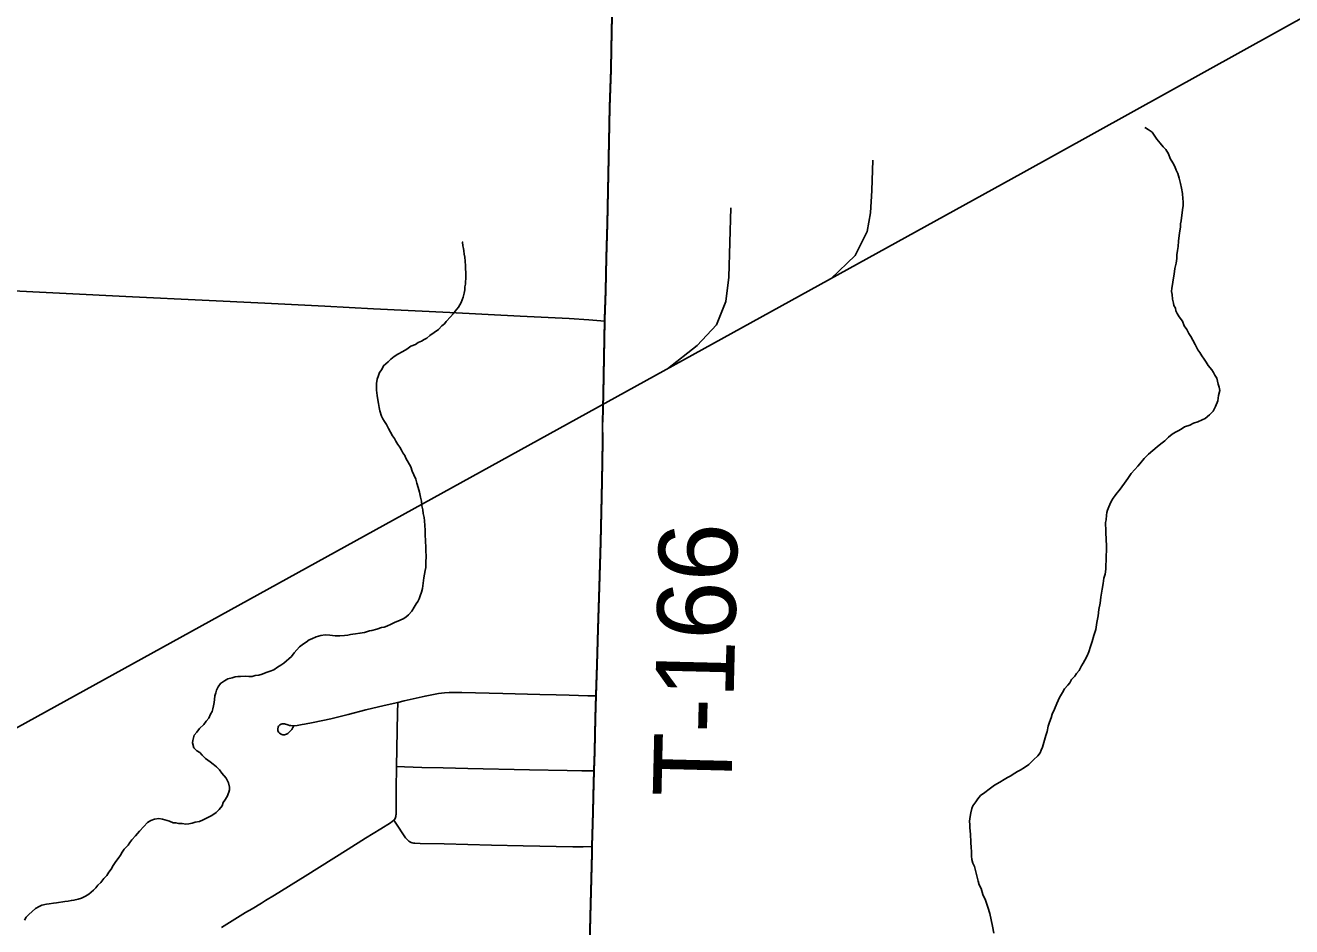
# Model space of a CAD drawing. Extents: x 0 to 34, y 0 to 22.
# Drawn here: x 28.463 to 29.379, y 19.256 to 19.908 of the extents above; entities that cross this region are included whole.
import ezdxf

# ---------------------------------------------------------------- set-up
doc = ezdxf.new("R2010")
doc.units = 0
for name, color, linetype in [('GM_X_City_Street', 7, 'Continuous'), ('GM_X_Minor_River', 7, 'Continuous'), ('GM_X_Rail_Line', 7, 'Continuous'), ('GM_X_Township_Road', 7, 'Continuous'), ('GM_X_Township_Road_Text', 7, 'Continuous')]:
    doc.layers.add(name, color=color, linetype=linetype)

msp = doc.modelspace()

# ---------------------------------------------------------------- linework, layer by layer
at = {"layer": 'GM_X_City_Street'}
for points in [[(28.13583, 19.73373), (28.14997, 19.7328), (28.17291, 19.73119), (28.20572, 19.72916), (28.23749, 19.72711), (28.27908, 19.72477), (28.3505, 19.72142), (28.43928, 19.71681), (28.54048, 19.71173), (28.59077, 19.70916), (28.63611, 19.70705), (28.67955, 19.70489), (28.71495, 19.70305), (28.77021, 19.7003), (28.82111, 19.69765), (28.85651, 19.69601), (28.87072, 19.69497), (28.88228, 19.69412)], [(28.65709, 19.40097), (28.65649, 19.39973), (28.65572, 19.39849), (28.65518, 19.39791), (28.65444, 19.39708), (28.65362, 19.39631), (28.65276, 19.39556), (28.65185, 19.39503), (28.65108, 19.39474), (28.65037, 19.39462), (28.64922, 19.39462), (28.64857, 19.39473), (28.64795, 19.39494), (28.64688, 19.39564), (28.6461, 19.39658), (28.64568, 19.39765), (28.6456, 19.39827), (28.64564, 19.39897), (28.64589, 19.40008), (28.64617, 19.4007), (28.64655, 19.40123), (28.647, 19.40169), (28.64798, 19.4023), (28.64862, 19.40249), (28.64926, 19.40259), (28.65049, 19.40255), (28.65288, 19.40173), (28.65403, 19.4014), (28.65502, 19.4012), (28.65646, 19.40108), (28.65953, 19.4013), (28.66319, 19.4019), (28.66499, 19.40229), (28.6711, 19.40344), (28.6839, 19.4062), (28.6966, 19.40927), (28.70924, 19.41259), (28.72256, 19.41568), (28.73245, 19.41802), (28.73709, 19.41911), (28.75224, 19.42262), (28.76199, 19.42452), (28.76612, 19.42501), (28.76961, 19.42521), (28.77871, 19.42523), (28.80856, 19.42455), (28.83528, 19.4238), (28.84709, 19.42342), (28.85641, 19.42315), (28.87008, 19.42289), (28.87602, 19.42278)], [(28.60482, 19.25512), (28.62218, 19.26582), (28.62691, 19.26866), (28.63367, 19.27272), (28.63677, 19.27458), (28.64313, 19.27844), (28.66531, 19.29223), (28.69643, 19.31166), (28.70902, 19.31967), (28.72014, 19.32648), (28.72714, 19.33089), (28.72965, 19.33282), (28.7301, 19.33332), (28.73047, 19.33393), (28.73071, 19.33459), (28.73096, 19.3355), (28.73112, 19.33627), (28.73121, 19.3369), (28.73125, 19.33764), (28.7312, 19.34268), (28.73114, 19.3551), (28.73154, 19.37149), (28.7323, 19.41042), (28.73245, 19.41802)], [(28.73154, 19.37149), (28.73735, 19.37133), (28.74975, 19.371), (28.76525, 19.37067), (28.78323, 19.37022), (28.82786, 19.36919), (28.85514, 19.36882), (28.86568, 19.36857), (28.87464, 19.36835)], [(28.72965, 19.33282), (28.73292, 19.32779), (28.73563, 19.32361), (28.73808, 19.32), (28.73889, 19.319), (28.73975, 19.31816), (28.74037, 19.3176), (28.74112, 19.31707), (28.74202, 19.31661), (28.74295, 19.31633), (28.74371, 19.31612), (28.74477, 19.31599), (28.74851, 19.31597), (28.76592, 19.31562), (28.80014, 19.31469), (28.82316, 19.31427), (28.85924, 19.31355), (28.86671, 19.31356), (28.87322, 19.31358)]]:
    msp.add_lwpolyline(points, dxfattribs=at)
at = {"layer": 'GM_X_Minor_River'}
for points in [[(29.25024, 19.56591), (29.25181, 19.56777), (29.253, 19.56963), (29.25458, 19.57149), (29.25655, 19.57409), (29.25853, 19.5767), (29.2609, 19.58005), (29.26329, 19.58378), (29.26604, 19.58674), (29.268, 19.58896), (29.26957, 19.59082), (29.27272, 19.59453), (29.27586, 19.59786), (29.27897, 19.60043), (29.28209, 19.603), (29.28481, 19.6052), (29.28753, 19.60741), (29.29027, 19.60999), (29.29299, 19.61219), (29.29531, 19.61364), (29.29724, 19.61473), (29.29955, 19.6158), (29.30189, 19.61763), (29.30571, 19.61866), (29.30842, 19.6201), (29.31149, 19.62116), (29.31457, 19.62259), (29.31687, 19.62366), (29.31999, 19.62623), (29.32272, 19.62881), (29.32434, 19.63219), (29.32598, 19.63632), (29.32647, 19.64011), (29.32734, 19.64388), (29.32703, 19.64617), (29.32634, 19.64847), (29.32532, 19.65268), (29.32387, 19.65501), (29.32278, 19.65694), (29.3217, 19.65887), (29.31913, 19.66198), (29.31768, 19.66431), (29.31623, 19.66663), (29.3144, 19.66896), (29.31295, 19.67129), (29.31148, 19.67323), (29.3097, 19.67708), (29.30789, 19.68017), (29.30645, 19.68288), (29.305, 19.6852), (29.30356, 19.6879), (29.30174, 19.69062), (29.30032, 19.69408), (29.29813, 19.69718), (29.29668, 19.69951), (29.29559, 19.70144), (29.29527, 19.70335), (29.29419, 19.70528), (29.29386, 19.70719), (29.29318, 19.70987), (29.2929, 19.7133), (29.29259, 19.71559), (29.29266, 19.71787), (29.29311, 19.72051), (29.29359, 19.72392), (29.29447, 19.72808), (29.29497, 19.73224), (29.29585, 19.73602), (29.29632, 19.73943), (29.2964, 19.74208), (29.29687, 19.74511), (29.29734, 19.74814), (29.29745, 19.75194), (29.29795, 19.7561), (29.29843, 19.75951), (29.29889, 19.76216), (29.29895, 19.76444), (29.2994, 19.7667), (29.30039, 19.77466), (29.30086, 19.77768), (29.30095, 19.78072), (29.30063, 19.78263), (29.30036, 19.78644), (29.29971, 19.79026), (29.29905, 19.7937), (29.29802, 19.79753), (29.29698, 19.80098), (29.29591, 19.80329), (29.29485, 19.80598), (29.29341, 19.80869), (29.2916, 19.81178), (29.29018, 19.81524), (29.28837, 19.81834), (29.28653, 19.82029), (29.28433, 19.82301), (29.28175, 19.82575), (29.27848, 19.83078), (29.2755, 19.83277), (29.27364, 19.83396), (29.27327, 19.83436)], [(28.75083, 19.50433), (28.75132, 19.50812), (28.75178, 19.51077), (28.75224, 19.51341), (28.75269, 19.51568), (28.75274, 19.51758), (28.75282, 19.52024), (28.75289, 19.5229), (28.75295, 19.5248), (28.75263, 19.52671), (28.75268, 19.52861), (28.75275, 19.53089), (28.75247, 19.53431), (28.75253, 19.53621), (28.7522, 19.53812), (28.75227, 19.5404), (28.75233, 19.54268), (28.75205, 19.54611), (28.75177, 19.54954), (28.75146, 19.55183), (28.75079, 19.55489), (28.75049, 19.55756), (28.74981, 19.56024), (28.74953, 19.56367), (28.74886, 19.56673), (28.7482, 19.57017), (28.74716, 19.57362), (28.74611, 19.57669), (28.74544, 19.57975), (28.74401, 19.58283), (28.74295, 19.58552), (28.7419, 19.5886), (28.73828, 19.59478), (28.73758, 19.5967), (28.73611, 19.59865), (28.73503, 19.60058), (28.73396, 19.60289), (28.7325, 19.60483), (28.73104, 19.60715), (28.72996, 19.60909), (28.7285, 19.61103), (28.72706, 19.61373), (28.72562, 19.61643), (28.72418, 19.61914), (28.72272, 19.62146), (28.72164, 19.62339), (28.72056, 19.62532), (28.71953, 19.62915), (28.71884, 19.63145), (28.71855, 19.6345), (28.71786, 19.63718), (28.71757, 19.64023), (28.71725, 19.64214), (28.71693, 19.64405), (28.71698, 19.64595), (28.71707, 19.64899), (28.71754, 19.65202), (28.71838, 19.65465), (28.7192, 19.65691), (28.72078, 19.65914), (28.722, 19.66177), (28.72551, 19.66471), (28.72746, 19.66655), (28.72979, 19.66839), (28.7325, 19.67021), (28.73597, 19.67201), (28.73907, 19.67382), (28.74179, 19.67602), (28.74524, 19.67706), (28.74718, 19.67853), (28.74949, 19.6796), (28.75142, 19.68069), (28.75335, 19.68177), (28.75569, 19.6836), (28.76189, 19.68798), (28.76425, 19.69058), (28.76619, 19.69204), (28.76738, 19.69391), (28.77052, 19.69724), (28.77248, 19.69946), (28.77406, 19.70132), (28.77642, 19.70429), (28.77842, 19.70765), (28.77967, 19.71142), (28.78052, 19.71443), (28.78096, 19.7167), (28.78103, 19.71898), (28.78146, 19.72087), (28.78152, 19.72277), (28.78157, 19.72466), (28.78163, 19.72656), (28.78171, 19.72922), (28.78141, 19.73189), (28.78147, 19.73417), (28.78119, 19.7376), (28.78089, 19.74027), (28.78058, 19.74256), (28.78027, 19.74485), (28.77994, 19.74676), (28.77962, 19.74867), (28.77932, 19.75134)], [(28.77932, 19.75134), (28.77932, 19.75134), (28.77894, 19.75135)], [(29.16395, 19.251), (29.16295, 19.25598), (29.16195, 19.26057), (29.16094, 19.26516), (29.15956, 19.26976), (29.1578, 19.27475), (29.15602, 19.27898), (29.15463, 19.28321), (29.15319, 19.28591), (29.15251, 19.28859), (29.14978, 19.29931), (29.14871, 19.30162), (29.14803, 19.3043), (29.14771, 19.30659), (29.14781, 19.31001), (29.14752, 19.31306), (29.14724, 19.31649), (29.14731, 19.31877), (29.14698, 19.32068), (29.14704, 19.32258), (29.14673, 19.32487), (29.14642, 19.32754), (29.14648, 19.32944), (29.14618, 19.33211), (29.14666, 19.33552), (29.14711, 19.33816), (29.14796, 19.34118), (29.14878, 19.34306), (29.15076, 19.34604), (29.15235, 19.34827), (29.15431, 19.3505), (29.15741, 19.35269), (29.16053, 19.35526), (29.16441, 19.35819), (29.16827, 19.36036), (29.17136, 19.36217), (29.17368, 19.36362), (29.17561, 19.36471), (29.1791, 19.36689), (29.18103, 19.36797), (29.18296, 19.36906), (29.18605, 19.37087), (29.18915, 19.37306), (29.19267, 19.37638), (29.19579, 19.37933), (29.19738, 19.38156), (29.19819, 19.38344), (29.19902, 19.3857), (29.20154, 19.39399), (29.20239, 19.397), (29.20326, 19.40078), (29.2041, 19.4038), (29.20533, 19.4068), (29.20617, 19.40944), (29.2078, 19.41319), (29.20944, 19.41733), (29.21146, 19.42145), (29.21346, 19.42519), (29.21506, 19.42781), (29.21741, 19.4304), (29.21899, 19.43226), (29.22019, 19.4345), (29.22255, 19.43709), (29.22374, 19.43896), (29.22571, 19.44118), (29.22732, 19.44456), (29.22852, 19.44642), (29.22972, 19.44867), (29.23133, 19.45166), (29.23256, 19.45467), (29.23381, 19.45844), (29.23505, 19.4622), (29.23632, 19.46634), (29.23759, 19.47087), (29.23849, 19.47579), (29.23939, 19.4807), (29.23991, 19.48525), (29.2408, 19.48978), (29.24131, 19.49433), (29.24223, 19.5), (29.24312, 19.50416), (29.24361, 19.50795), (29.24445, 19.51096), (29.24493, 19.51437), (29.24502, 19.51741), (29.24512, 19.52083), (29.24522, 19.52425), (29.24533, 19.52804), (29.24542, 19.53108), (29.24495, 19.54098), (29.24504, 19.54402), (29.24472, 19.54631), (29.24478, 19.54821), (29.24521, 19.55009), (29.24532, 19.55351), (29.24575, 19.5554), (29.24619, 19.55729), (29.24701, 19.55954), (29.24782, 19.56142), (29.24904, 19.56405), (29.25024, 19.56591)], [(28.6009, 19.33836), (28.60324, 19.34058), (28.60521, 19.34318), (28.60604, 19.34544), (28.60723, 19.34731), (28.60883, 19.34992), (28.61006, 19.35293), (28.61049, 19.35481), (28.61055, 19.35671), (28.60988, 19.35977), (28.60808, 19.36325), (28.60514, 19.36675), (28.60331, 19.36909), (28.6011, 19.37143), (28.59888, 19.3734), (28.59664, 19.37498), (28.59329, 19.37736), (28.59071, 19.37971), (28.58924, 19.38166), (28.587, 19.38286), (28.58479, 19.38521), (28.58375, 19.38866), (28.58418, 19.39055), (28.58462, 19.39243), (28.58505, 19.39432), (28.58702, 19.39655), (28.58899, 19.39915), (28.59212, 19.4021), (28.5937, 19.40434), (28.59567, 19.40656), (28.59689, 19.40957), (28.59809, 19.41143), (28.59852, 19.41332), (28.59897, 19.41559), (28.59941, 19.41786), (28.59986, 19.42012), (28.59994, 19.42278), (28.60076, 19.42504), (28.6012, 19.42693), (28.6024, 19.42917), (28.604, 19.43179), (28.60709, 19.4336), (28.60941, 19.43505), (28.61247, 19.43573), (28.61477, 19.43642), (28.61668, 19.43674), (28.61857, 19.43669), (28.622, 19.43697), (28.62466, 19.43689), (28.62694, 19.43683), (28.62923, 19.43752), (28.6319, 19.43782), (28.6342, 19.43852), (28.63727, 19.43957), (28.63996, 19.44063), (28.64265, 19.4417), (28.64536, 19.44352), (28.64768, 19.44497), (28.65001, 19.44643), (28.65546, 19.45121), (28.65744, 19.45381), (28.6594, 19.45604), (28.66137, 19.45826), (28.66409, 19.46046), (28.66602, 19.46155), (28.66835, 19.46338), (28.67027, 19.46409), (28.67335, 19.46552), (28.6768, 19.46656), (28.67985, 19.46685), (28.68327, 19.46675), (28.68705, 19.46626), (28.69047, 19.46616), (28.69389, 19.46644), (28.69618, 19.46676), (28.69809, 19.46708), (28.7, 19.46741), (28.70191, 19.46773), (28.70495, 19.46803), (28.70839, 19.46869), (28.71184, 19.46973), (28.71375, 19.47005), (28.7172, 19.47109), (28.72065, 19.47213), (28.72256, 19.47246), (28.72448, 19.47316), (28.72756, 19.47459), (28.73064, 19.47603), (28.73256, 19.47673), (28.73641, 19.47852), (28.73834, 19.47961), (28.74029, 19.48145), (28.74265, 19.48404), (28.74425, 19.48704), (28.74584, 19.48927), (28.74703, 19.49114), (28.74785, 19.49302), (28.74867, 19.49527), (28.74951, 19.49791), (28.75034, 19.50055), (28.75083, 19.50433)], [(28.46226, 19.26025), (28.46346, 19.2625), (28.46542, 19.26434), (28.46776, 19.26656), (28.4701, 19.26877), (28.4728, 19.27021), (28.47473, 19.2713), (28.47817, 19.27196), (28.48008, 19.27228), (28.48313, 19.27258), (28.48542, 19.27289), (28.49152, 19.27385), (28.49381, 19.27417), (28.4961, 19.27448), (28.49801, 19.27481), (28.50107, 19.27548), (28.50336, 19.27617), (28.50645, 19.27761), (28.50877, 19.27906), (28.51227, 19.282), (28.51384, 19.28385), (28.51542, 19.28571), (28.51737, 19.28755), (28.51974, 19.29053), (28.5217, 19.29275), (28.52328, 19.29499), (28.52487, 19.29722), (28.52646, 19.29984), (28.52845, 19.30282), (28.53003, 19.30506), (28.53162, 19.30729), (28.53282, 19.30954), (28.53441, 19.31177), (28.53715, 19.31473), (28.53835, 19.3166), (28.53992, 19.31846), (28.54267, 19.32142), (28.54542, 19.32476), (28.54856, 19.32809), (28.5513, 19.33105), (28.55362, 19.33251), (28.55631, 19.33357), (28.55936, 19.33386), (28.56201, 19.3334), (28.56729, 19.33211), (28.56991, 19.3309), (28.57181, 19.33084), (28.5737, 19.33041), (28.57635, 19.33033), (28.579, 19.32987), (28.58129, 19.33019), (28.58357, 19.3305), (28.58587, 19.3312), (28.58893, 19.33187), (28.59162, 19.33293), (28.59355, 19.33401), (28.59586, 19.33509), (28.59779, 19.33617), (28.6009, 19.33836)]]:
    msp.add_lwpolyline(points, dxfattribs=at)
at = {"layer": 'GM_X_Rail_Line'}
for points in [[(26.77525, 17.99218), (26.84574, 18.02958), (26.89547, 18.06061), (26.9486, 18.09333), (26.99087, 18.12212), (27.08532, 18.1905), (27.21214, 18.29488), (27.38363, 18.4394), (27.44818, 18.50107), (27.48656, 18.54586), (27.5232, 18.586), (27.56216, 18.66395), (27.58616, 18.71125), (27.67905, 18.89432), (27.70173, 18.94027), (27.72383, 18.97169), (27.75291, 18.99728), (27.81688, 19.03917), (28.26175, 19.29222), (29.18349, 19.80066), (29.90227, 20.19973)], [(29.04581, 19.7247), (29.06345, 19.74153), (29.07216, 19.75892), (29.0746, 19.77244), (29.07555, 19.78876), (29.0763, 19.81063)], [(28.92772, 19.65955), (28.94917, 19.67635), (28.9631, 19.69148), (28.96994, 19.70829), (28.97215, 19.72582), (28.97349, 19.77604)]]:
    msp.add_lwpolyline(points, dxfattribs=at)
at = {"layer": 'GM_X_Township_Road'}
msp.add_line((28.87407, 19.34975), (28.87464, 19.36835), dxfattribs=at)
for points in [[(28.88228, 19.69412), (28.88229, 19.69519), (28.88298, 19.7157), (28.88355, 19.73994), (28.8842, 19.76417), (28.885, 19.80021), (28.88532, 19.82384), (28.88598, 19.84871), (28.88677, 19.87606), (28.88719, 19.89097), (28.88789, 19.927), (28.88866, 19.95622), (28.88971, 19.99363), (28.89045, 20.03607)], [(28.87109, 19.24332), (28.87156, 19.26305), (28.87287, 19.309), (28.87298, 19.31413), (28.87352, 19.33882), (28.87383, 19.3503), (28.8744, 19.3689), (28.87479, 19.38277), (28.87532, 19.40699), (28.87579, 19.42333), (28.8758, 19.42375), (28.87642, 19.44548), (28.8773, 19.47155), (28.87815, 19.50196), (28.87906, 19.53423), (28.88002, 19.5783), (28.88052, 19.60748), (28.88049, 19.62075), (28.88099, 19.64166), (28.88204, 19.69467), (28.88206, 19.69574), (28.88275, 19.71625), (28.88331, 19.74049), (28.88396, 19.76472), (28.88476, 19.80077), (28.88509, 19.82439), (28.88574, 19.84926), (28.88654, 19.87661), (28.88696, 19.89152), (28.88765, 19.92756)], [(28.88765, 19.92756), (28.88696, 19.89152), (28.88654, 19.87661), (28.88574, 19.84926), (28.88509, 19.82439), (28.88476, 19.80077), (28.88396, 19.76472), (28.88331, 19.74049), (28.88275, 19.71625), (28.88206, 19.69574), (28.88204, 19.69467), (28.88099, 19.64166), (28.88049, 19.62075), (28.88052, 19.60748), (28.88002, 19.5783), (28.87906, 19.53423), (28.87815, 19.50196), (28.8773, 19.47155), (28.87642, 19.44548), (28.8758, 19.42375), (28.87579, 19.42333), (28.87532, 19.40699), (28.87479, 19.38277), (28.8744, 19.3689), (28.87383, 19.3503), (28.87352, 19.33882), (28.87298, 19.31413), (28.87287, 19.309), (28.87156, 19.26305), (28.87109, 19.24332)], [(28.88075, 19.62119), (28.88123, 19.64111), (28.88228, 19.69412)], [(28.87602, 19.42278), (28.87665, 19.44493), (28.87753, 19.47099), (28.87838, 19.5014), (28.8793, 19.53368), (28.88026, 19.57775), (28.88075, 19.60692), (28.88072, 19.6202), (28.88075, 19.62119)], [(28.87464, 19.36835), (28.87502, 19.38222), (28.87555, 19.40644), (28.87602, 19.42278)], [(28.87322, 19.31358), (28.87376, 19.33827), (28.87407, 19.34975)], [(28.87133, 19.24276), (28.8718, 19.26249), (28.8731, 19.30844), (28.87322, 19.31358)]]:
    msp.add_lwpolyline(points, dxfattribs=at)

# ---------------------------------------------------------------- texts
at = {"layer": 'GM_X_Township_Road_Text'}
msp.add_text('T-166', height=0.056818, rotation=88.59448, dxfattribs=at).set_placement((28.97374, 19.34892))

doc.saveas('drawing.dxf')
